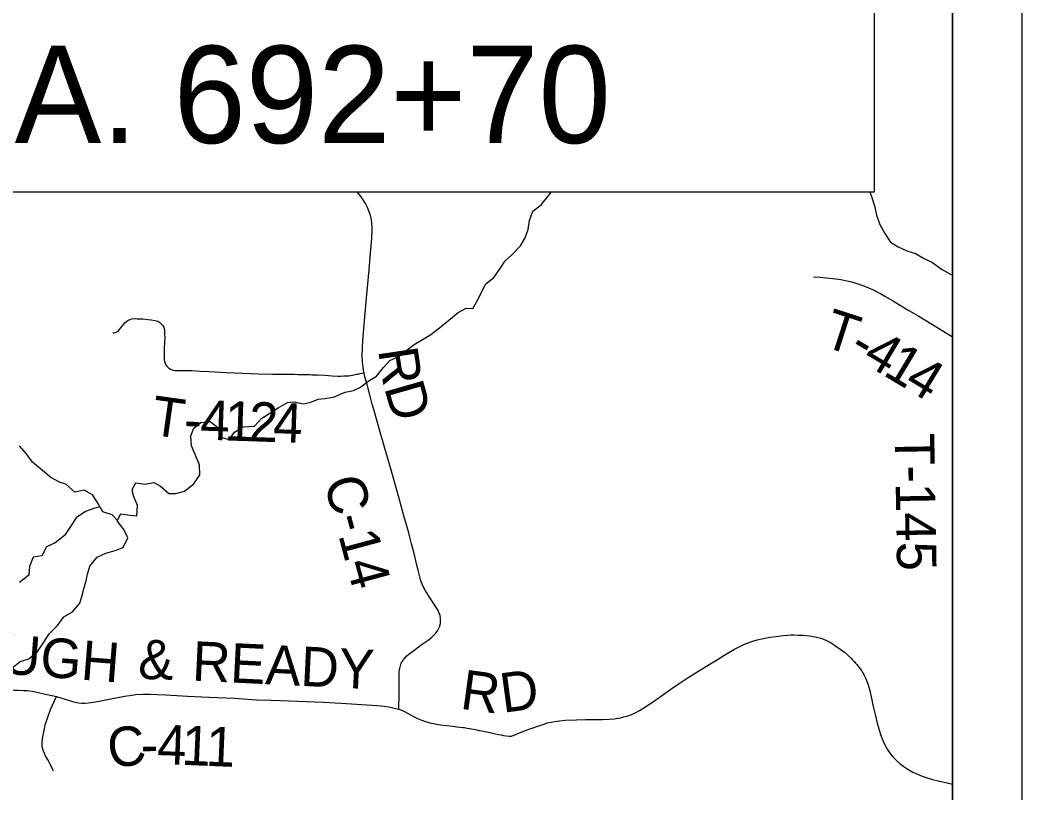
# Model space of a CAD drawing. Extents: x 0 to 34, y 0 to 22.
# Drawn here: x 29.474 to 30.917, y 15.055 to 16.168 of the extents above; entities that cross this region are included whole.
import ezdxf

# ---------------------------------------------------------------- set-up
doc = ezdxf.new("R2010")
doc.units = 0
for name, color, linetype in [('GM_X_Adjacent_County', 7, 'Continuous'), ('GM_X_County', 7, 'Continuous'), ('GM_X_County_Road', 7, 'Continuous'), ('GM_X_County_Road_Text', 7, 'Continuous'), ('GM_X_Minor_River', 7, 'Continuous'), ('GM_X_Township', 7, 'Continuous'), ('GM_X_Township_Road', 7, 'Continuous'), ('GM_X_Township_Road_Text', 7, 'Continuous'), ('SH_Data', 7, 'Continuous'), ('SH_Text', 7, 'Continuous')]:
    doc.layers.add(name, color=color, linetype=linetype)

msp = doc.modelspace()

# ---------------------------------------------------------------- linework, layer by layer
at = {"layer": 'GM_X_Adjacent_County'}
msp.add_lwpolyline([(28.5181, 14.1), (30.8167, 14.1), (30.8167, 20.9), (28.7526, 20.9)], dxfattribs=at)
at = {"layer": 'GM_X_County'}
msp.add_lwpolyline([(28.5181, 14.1), (30.8167, 14.1), (30.8167, 20.9), (28.7526, 20.9)], dxfattribs=at)
at = {"layer": 'GM_X_County_Road'}
for points in [[(29.9691, 15.6598), (29.9689, 15.6607), (29.9678, 15.6673), (29.9669, 15.6753), (29.9666, 15.684), (29.9667, 15.6945), (29.9674, 15.7062), (29.9703, 15.7402), (29.9731, 15.7724), (29.9764, 15.8077), (29.9785, 15.8318), (29.9797, 15.8479), (29.9806, 15.8628), (29.9806, 15.8709), (29.9804, 15.8746), (29.9797, 15.8802), (29.9782, 15.8863), (29.9765, 15.8916), (29.9741, 15.8974), (29.971, 15.9035), (29.9679, 15.9088), (29.965, 15.9129), (29.9594, 15.9203), (29.9594, 15.9204)], [(30.0191, 15.1753), (30.0193, 15.1809), (30.0197, 15.1918), (30.0198, 15.2072), (30.0196, 15.217), (30.0198, 15.2238), (30.0198, 15.229), (30.0205, 15.2339), (30.0216, 15.2379), (30.0228, 15.2417), (30.0238, 15.2437), (30.0249, 15.2455), (30.0273, 15.2484), (30.0305, 15.252), (30.0341, 15.255), (30.0373, 15.2575), (30.0429, 15.2615), (30.0514, 15.2678), (30.0584, 15.2727), (30.0615, 15.2749), (30.0659, 15.2783), (30.0696, 15.2817), (30.0725, 15.285), (30.0748, 15.2881), (30.077, 15.292), (30.0777, 15.2937), (30.0787, 15.2968), (30.0791, 15.2993), (30.0794, 15.3025), (30.0791, 15.3063), (30.0785, 15.3101), (30.0775, 15.3137), (30.076, 15.3173), (30.0736, 15.3215), (30.0697, 15.3272), (30.0671, 15.3311), (30.066, 15.3326), (30.0643, 15.3351), (30.0613, 15.3397), (30.0595, 15.3428), (30.0576, 15.3459), (30.054, 15.3529), (30.0511, 15.3603), (30.0484, 15.3697), (30.047, 15.3757), (30.0452, 15.3829), (30.0437, 15.3889), (30.0421, 15.3955), (30.0392, 15.4069), (30.0375, 15.4136), (30.0349, 15.4232), (30.0334, 15.4292), (30.0266, 15.4538), (30.0196, 15.4789), (30.0095, 15.5148), (29.9935, 15.5709), (29.983, 15.6067), (29.9809, 15.6144), (29.9778, 15.6258), (29.9734, 15.6426), (29.9704, 15.654), (29.9691, 15.6598)], [(30.0191, 15.1753), (30.0192, 15.1753), (30.0233, 15.1738), (30.0272, 15.172), (30.0403, 15.1648), (30.0459, 15.162), (30.051, 15.1598), (30.0574, 15.1575), (30.064, 15.1557), (30.0713, 15.1542), (30.0787, 15.153), (30.0972, 15.1508), (30.1027, 15.1501), (30.107, 15.1496), (30.1113, 15.1491), (30.114, 15.1488), (30.1175, 15.1482), (30.121, 15.1475), (30.1268, 15.1464), (30.1315, 15.1455), (30.135, 15.1448), (30.1386, 15.1441), (30.1433, 15.1431), (30.148, 15.1422), (30.1527, 15.1412), (30.1586, 15.14), (30.1628, 15.139), (30.1665, 15.1383), (30.1701, 15.1377), (30.1783, 15.1366), (30.1808, 15.1367), (30.1838, 15.1376), (30.187, 15.1388), (30.1918, 15.1407), (30.1977, 15.1431), (30.2005, 15.1443), (30.2081, 15.1472), (30.2127, 15.1487), (30.2179, 15.1505), (30.2238, 15.1524), (30.2273, 15.1535), (30.2332, 15.1555), (30.2386, 15.1567), (30.2441, 15.1578), (30.2508, 15.1588), (30.2589, 15.1594), (30.275, 15.16), (30.2881, 15.1605), (30.2955, 15.1606), (30.3029, 15.1606), (30.3073, 15.1607), (30.3128, 15.1607), (30.322, 15.1611), (30.3293, 15.1617), (30.3349, 15.1624), (30.3385, 15.1631), (30.3434, 15.1642), (30.3476, 15.1653), (30.3534, 15.1674), (30.3597, 15.1701), (30.3657, 15.1733), (30.3721, 15.1771), (30.3819, 15.1837), (30.3942, 15.1922), (30.4109, 15.2041), (30.4201, 15.2104), (30.4361, 15.2208), (30.4498, 15.2294), (30.466, 15.2397), (30.4766, 15.2461), (30.4873, 15.2525), (30.4947, 15.257), (30.5027, 15.2617), (30.5082, 15.2647), (30.5144, 15.2676), (30.5195, 15.2698), (30.5277, 15.2727), (30.5354, 15.275), (30.5445, 15.2771), (30.5536, 15.2789), (30.5629, 15.2802), (30.5727, 15.2813), (30.5783, 15.2819), (30.5839, 15.2822), (30.5882, 15.2822), (30.5944, 15.2821), (30.6012, 15.2819), (30.6062, 15.2815), (30.6111, 15.2811), (30.616, 15.2802), (30.6209, 15.2792), (30.6268, 15.2775), (30.6333, 15.2751), (30.6372, 15.2733), (30.6409, 15.2712), (30.6437, 15.2696), (30.6469, 15.2675), (30.655, 15.2619), (30.6609, 15.2574), (30.6665, 15.2525), (30.671, 15.2483), (30.6722, 15.247), (30.6747, 15.2444), (30.6751, 15.2439), (30.6771, 15.2417), (30.6787, 15.2398), (30.6818, 15.236), (30.6854, 15.2309), (30.6871, 15.2283), (30.6883, 15.2262), (30.6895, 15.2241), (30.6898, 15.2236), (30.6908, 15.2214), (30.6918, 15.2192), (30.6947, 15.2117), (30.6962, 15.207), (30.6976, 15.2016), (30.7004, 15.1888), (30.7015, 15.1834), (30.703, 15.1773), (30.7051, 15.1676), (30.7082, 15.155), (30.7108, 15.1454), (30.7129, 15.1389), (30.7153, 15.1325), (30.7172, 15.128), (30.7199, 15.1224), (30.7227, 15.1176), (30.7254, 15.1135), (30.7267, 15.1117), (30.7277, 15.1103), (30.7284, 15.1095), (30.7302, 15.1073), (30.7339, 15.1033), (30.7358, 15.1014), (30.7366, 15.1008), (30.7411, 15.0969), (30.7466, 15.0927), (30.7522, 15.0889), (30.7593, 15.0849), (30.766, 15.0816), (30.7729, 15.0788), (30.7799, 15.0764), (30.7877, 15.0743), (30.7962, 15.0722), (30.8107, 15.0688), (30.8167, 15.0676)], [(29.3084, 15.2131), (29.3157, 15.2126), (29.3176, 15.2124), (29.3238, 15.2121), (29.335, 15.2116), (29.358, 15.2108), (29.3772, 15.21), (29.394, 15.2092), (29.4076, 15.2081), (29.4192, 15.2068), (29.4241, 15.2062), (29.4303, 15.2053), (29.4376, 15.2044), (29.4475, 15.2035), (29.4561, 15.2031), (29.4648, 15.2029), (29.471, 15.2027), (29.4791, 15.2024), (29.4841, 15.2021), (29.4909, 15.2011), (29.4982, 15.1998), (29.5059, 15.1981), (29.5129, 15.1967), (29.5262, 15.1936)], [(29.5262, 15.1936), (29.5385, 15.1898), (29.549, 15.1865), (29.5549, 15.1851), (29.5585, 15.1845), (29.5627, 15.1842), (29.5675, 15.1842), (29.576, 15.185), (29.5851, 15.1864), (29.5899, 15.1873), (29.6067, 15.1907), (29.624, 15.1941), (29.6313, 15.1953), (29.6406, 15.1964), (29.6505, 15.1969), (29.661, 15.1968), (29.6716, 15.1965), (29.6834, 15.1959), (29.707, 15.1946), (29.715, 15.1941), (29.7461, 15.1929), (29.7827, 15.191), (29.8143, 15.189), (29.8354, 15.1884), (29.8739, 15.1867), (29.9105, 15.1854), (29.936, 15.1839), (29.9657, 15.1821), (29.9874, 15.1806), (29.9979, 15.1797), (30.0047, 15.1787), (30.0126, 15.177), (30.0191, 15.1753)]]:
    msp.add_lwpolyline(points, dxfattribs=at)
at = {"layer": 'GM_X_Minor_River'}
for points in [[(30.0804, 15.7264), (30.091, 15.7356), (30.1045, 15.7467), (30.1162, 15.7528), (30.1257, 15.7521), (30.1336, 15.7655), (30.1396, 15.7784), (30.1444, 15.7879), (30.1558, 15.7971), (30.1644, 15.8086), (30.1723, 15.8208), (30.1821, 15.8296), (30.1945, 15.8426), (30.2012, 15.854), (30.2057, 15.8658), (30.2075, 15.8791), (30.2124, 15.8924), (30.224, 15.9016), (30.2361, 15.9165), (30.2391, 15.9204)], [(30.6977, 15.9204), (30.7006, 15.9122), (30.7044, 15.9), (30.7072, 15.8864)], [(30.7072, 15.8864), (30.7122, 15.8731), (30.7191, 15.8603), (30.7272, 15.8478), (30.7386, 15.8411), (30.7508, 15.8351), (30.7633, 15.8314), (30.7747, 15.8246), (30.7876, 15.8186), (30.801, 15.8089), (30.8139, 15.8017), (30.8167, 15.8005)], [(29.4616, 15.2343), (29.4737, 15.2439), (29.4865, 15.2478), (29.4993, 15.2589), (29.508, 15.2719), (29.5155, 15.2837), (29.5275, 15.2959), (29.5369, 15.3081), (29.549, 15.3154), (29.5599, 15.328), (29.5625, 15.3375), (29.5658, 15.3505), (29.5688, 15.36), (29.5706, 15.3698), (29.5743, 15.3813), (29.5849, 15.3942), (29.5973, 15.4), (29.6106, 15.4039), (29.6223, 15.4082), (29.6287, 15.4219), (29.6233, 15.434), (29.6137, 15.4464), (29.6189, 15.4567), (29.6322, 15.4545), (29.6421, 15.4538), (29.6427, 15.4687), (29.637, 15.4823), (29.635, 15.4918), (29.6406, 15.5013), (29.6539, 15.4991), (29.6664, 15.5018), (29.6759, 15.4966), (29.6881, 15.486), (29.698, 15.4861), (29.7105, 15.4892), (29.724, 15.5), (29.7327, 15.5129), (29.7322, 15.5273), (29.7206, 15.5546), (29.7194, 15.569), (29.7239, 15.58), (29.7341, 15.5881), (29.7473, 15.5897), (29.7599, 15.5799), (29.7638, 15.5667), (29.7748, 15.5637), (29.7827, 15.574), (29.7951, 15.5821), (29.8114, 15.5829), (29.822, 15.5944), (29.8318, 15.6005), (29.8454, 15.6094), (29.859, 15.617), (29.8685, 15.6179), (29.8821, 15.6149), (29.8923, 15.6176), (29.9029, 15.6215), (29.9128, 15.6227), (29.9253, 15.6247), (29.9419, 15.6317), (29.954, 15.6344), (29.9638, 15.639), (29.9752, 15.6474), (29.9869, 15.6547), (29.997, 15.6673), (30.0061, 15.6776), (30.0185, 15.683), (30.0291, 15.6915), (30.0412, 15.7003), (30.0517, 15.7064), (30.0653, 15.7149), (30.0804, 15.7264)], [(29.6141, 15.4472), (29.6064, 15.4551), (29.5931, 15.4596), (29.5851, 15.4728), (29.5778, 15.4842), (29.566, 15.4905), (29.5528, 15.4878), (29.5398, 15.4995), (29.5303, 15.5024), (29.5181, 15.5088), (29.5032, 15.5212), (29.4918, 15.531), (29.4826, 15.5435), (29.4731, 15.5544)], [(29.5889, 15.4665), (29.5813, 15.4648), (29.5681, 15.4602), (29.5545, 15.451), (29.5463, 15.4384), (29.5376, 15.4254), (29.5244, 15.4151), (29.5116, 15.4089), (29.5052, 15.396), (29.4927, 15.394), (29.4871, 15.3807), (29.4861, 15.3685), (29.4729, 15.3578)]]:
    msp.add_lwpolyline(points, dxfattribs=at)
at = {"layer": 'GM_X_Township'}
msp.add_lwpolyline([(28.5181, 14.1), (30.8167, 14.1), (30.8167, 18.1651)], dxfattribs=at)
at = {"layer": 'GM_X_Township_Road'}
for points in [[(30.6165, 15.7977), (30.6258, 15.7972), (30.6441, 15.7954), (30.6558, 15.7938), (30.6644, 15.7923), (30.6717, 15.7906), (30.6788, 15.7884), (30.6887, 15.7848), (30.7012, 15.7794), (30.7063, 15.777), (30.7096, 15.7754), (30.7129, 15.7736), (30.7193, 15.77), (30.7316, 15.7628), (30.7428, 15.7561), (30.7538, 15.7495), (30.7682, 15.7412), (30.7767, 15.7361), (30.8025, 15.72), (30.8167, 15.7115)], [(29.6075, 15.7171), (29.6089, 15.7174), (29.6102, 15.7177), (29.6122, 15.7183), (29.6138, 15.7189), (29.615, 15.7197), (29.6164, 15.7213), (29.6188, 15.7245), (29.6205, 15.7267), (29.6224, 15.7289), (29.6252, 15.7322), (29.6274, 15.734), (29.6289, 15.735), (29.6305, 15.7359), (29.6322, 15.7366), (29.6346, 15.7373), (29.6378, 15.7376), (29.6423, 15.7375), (29.6464, 15.7375), (29.6507, 15.7372), (29.6577, 15.7364), (29.6626, 15.7359), (29.6678, 15.7351), (29.67, 15.7345), (29.6719, 15.7339), (29.6737, 15.733), (29.675, 15.7322), (29.6766, 15.7306), (29.6782, 15.7289), (29.6792, 15.7277), (29.6801, 15.7263), (29.6808, 15.7249), (29.6813, 15.7233), (29.6817, 15.7211), (29.6818, 15.7189), (29.6819, 15.7161), (29.682, 15.7095), (29.6813, 15.696), (29.681, 15.6911), (29.681, 15.6862), (29.6812, 15.6818), (29.6814, 15.6785), (29.6819, 15.6758), (29.6828, 15.6734), (29.6838, 15.6711), (29.6847, 15.6695), (29.6858, 15.6681), (29.6869, 15.6671), (29.688, 15.6662), (29.6892, 15.6653), (29.6903, 15.6647), (29.6916, 15.6642), (29.6942, 15.6635), (29.6972, 15.6631), (29.7004, 15.6631), (29.7213, 15.6629), (29.7332, 15.6622), (29.7455, 15.6616), (29.7703, 15.6603), (29.7832, 15.6598), (29.817, 15.6584), (29.8376, 15.6578), (29.8532, 15.6577), (29.8631, 15.6578), (29.8693, 15.6576), (29.8742, 15.6574), (29.8841, 15.6571), (29.8904, 15.657), (29.8941, 15.6569), (29.9022, 15.6566), (29.9127, 15.6561), (29.9232, 15.6555), (29.9313, 15.655), (29.935, 15.655), (29.9399, 15.6551), (29.9431, 15.6552), (29.947, 15.6555), (29.9498, 15.6559), (29.9523, 15.6563), (29.9565, 15.6571), (29.9583, 15.6575), (29.96, 15.6578), (29.9621, 15.6582), (29.9633, 15.6585), (29.9691, 15.6598)], [(29.5219, 15.0861), (29.5201, 15.0901), (29.5179, 15.0945), (29.5156, 15.0989), (29.5132, 15.1032), (29.5105, 15.108), (29.5089, 15.1114), (29.5075, 15.1148), (29.5065, 15.1178), (29.5057, 15.1214), (29.5055, 15.1239), (29.5055, 15.127), (29.5062, 15.1331), (29.5087, 15.1472), (29.5099, 15.1526), (29.5121, 15.1597), (29.5141, 15.1655), (29.5176, 15.1748), (29.5203, 15.181), (29.5262, 15.1936)]]:
    msp.add_lwpolyline(points, dxfattribs=at)
at = {"layer": 'SH_Data'}
for points in [[(23.9167, 21), (30.9167, 21), (30.9167, 14), (23.9167, 14)], [(24.0167, 20.9), (30.8167, 20.9), (30.8167, 14.1), (24.0167, 14.1)]]:
    msp.add_lwpolyline(points, close=True, dxfattribs=at)
at = {"layer": 'SH_Text'}
msp.add_lwpolyline([(29.1566, 15.9204), (30.7042, 15.9204), (30.7042, 16.4104), (29.1566, 16.4104)], close=True, dxfattribs=at)

# ---------------------------------------------------------------- texts
at = {"layer": 'GM_X_County_Road_Text'}
for s, height, rotation, p in [('R', 0.0568, 278.4293, (29.9893, 15.6926)), ('D', 0.0568, 285.95, (29.9978, 15.6386)), ('C-14', 0.05682, 285.0934, (29.9109, 15.5037)), ('ROUGH', 0.05682, 355.5568, (29.3329, 15.2357)), ('&', 0.0568, 358.453, (29.6434, 15.2191)), ('READY', 0.05682, 357.2267, (29.7207, 15.2166)), ('R', 0.0568, 352.2287, (30.1063, 15.1763)), ('D', 0.0568, 7.7875, (30.1691, 15.17)), ('C', 0.0568, 7.2751, (29.6032, 15.0902)), ('4', 0.0568, 358.1314, (29.6704, 15.0965)), ('1', 0.0568, 357.569, (29.7053, 15.0954)), ('1', 0.0568, 357.6731, (29.7403, 15.0939)), ('-', 0.0568, 1.3271, (29.6479, 15.0959))]:
    msp.add_text(s, height=height, rotation=rotation, dxfattribs=at).set_placement(p)
at = {"layer": 'GM_X_Township_Road_Text'}
for s, height, rotation, p in [('T', 0.0568, 342.0828, (30.6273, 15.6987)), ('-', 0.0568, 329.6548, (30.6648, 15.687)), ('4', 0.0568, 329.088, (30.6848, 15.6753)), ('1', 0.0568, 329.0229, (30.7148, 15.6573)), ('4', 0.0568, 328.7989, (30.7447, 15.6393)), ('T', 0.0568, 351.9463, (29.6603, 15.5709)), ('4', 0.0568, 357.9544, (29.7325, 15.5637)), ('1', 0.0568, 358.002, (29.7675, 15.5624)), ('2', 0.0568, 358.0063, (29.8025, 15.5612)), ('4', 0.0568, 358.0193, (29.8375, 15.56)), ('-', 0.0568, 358.4076, (29.7093, 15.5643)), ('T-145', 0.05682, 270.9887, (30.7335, 15.5725))]:
    msp.add_text(s, height=height, rotation=rotation, dxfattribs=at).set_placement(p)
at = {"layer": 'SH_Text'}
msp.add_text('STA. 692+70', height=0.14, dxfattribs=at).set_placement((29.2266, 15.9904))

doc.saveas('drawing.dxf')
